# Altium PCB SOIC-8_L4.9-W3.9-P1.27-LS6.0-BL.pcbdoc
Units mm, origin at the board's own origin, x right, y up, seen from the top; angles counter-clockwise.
Board outline 17.75 x 19.75 mm, 2 copper layers (Top Layer, Bottom Layer), stack 0.07 mm thick; 1 components, 0 nets, 8 pads, 0 vias.
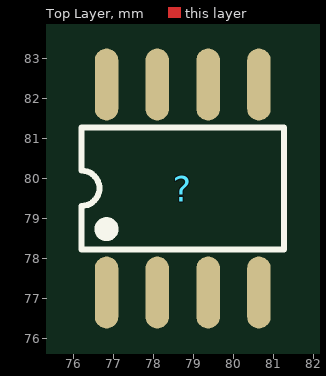
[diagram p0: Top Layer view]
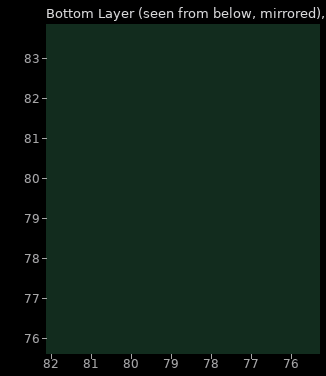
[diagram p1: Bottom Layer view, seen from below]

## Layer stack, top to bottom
Top Solder Mask Layer: solder mask 0.01, Dk 3.3
Top Layer: signal copper 0.035
Bottom Layer: signal copper 0.035
Bottom Solder Mask Layer: solder mask 0.01, Dk 3.3

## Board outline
87.602,69.85 69.85,69.85 69.85,89.6 87.602,89.6

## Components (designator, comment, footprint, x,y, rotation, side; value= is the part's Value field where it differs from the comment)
? "SOIC-8_L4.9-W3.9-P1.27-LS6.0-BL" SOIC-8_L4.9-W3.9-P1.27-LS6.0-BL 78.726,79.75 r0 top

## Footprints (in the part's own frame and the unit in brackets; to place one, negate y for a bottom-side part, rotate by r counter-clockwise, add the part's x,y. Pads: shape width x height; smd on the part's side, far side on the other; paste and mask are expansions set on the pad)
SOIC-8_L4.9-W3.9-P1.27-LS6.0-BL [mm]
  oval 0.588x1.8 smd paste+0 mask+0.051: 1(-1.905,-2.6) 2(-0.635,-2.6) 3(0.635,-2.6) 4(1.905,-2.6) 5(1.905,2.6) 6(0.635,2.6) 7(-0.635,2.6) 8(-1.905,2.6)
  silkscreen extent -2.53,-1.52 2.53,1.52

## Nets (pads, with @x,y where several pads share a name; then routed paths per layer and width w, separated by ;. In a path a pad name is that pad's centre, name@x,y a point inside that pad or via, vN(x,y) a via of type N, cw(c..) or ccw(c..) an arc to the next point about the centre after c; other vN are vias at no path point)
pads on no net: ?.1 ?.2 ?.3 ?.4 ?.5 ?.6 ?.7 ?.8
